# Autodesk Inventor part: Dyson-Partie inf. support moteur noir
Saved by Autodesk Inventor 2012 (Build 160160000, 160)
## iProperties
Created: 2012-11
Part Number: Dyson-Partie inf. support moteur noir
Material: Default
Document SubType Name: Modeling
Designer: Administrateur
Density: 1 g/cm^3
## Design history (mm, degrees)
node "Dyson-Partie inf. support moteur noir1"
node "Dyson-Partie inf. support moteur noir"
node "Base1"
